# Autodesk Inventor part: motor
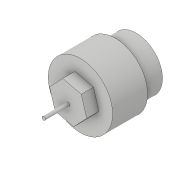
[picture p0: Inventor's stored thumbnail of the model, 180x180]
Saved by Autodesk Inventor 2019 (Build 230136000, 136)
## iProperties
Created: 2019-10
Part Number: motor
Material: Generic
Document SubType Name: Modeling
Designer: hp
Density: 1 g/cm^3
Appearance: Default
Author: hp
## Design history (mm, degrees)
sketch "Sketch1"
  geometry: C1 r 18.449 at (0, 0); 7 further points
  constraints: 1 centre point, 1 coincident
  dimensions: "d0" = 30 distance of point (24.8, -27.876) point (-5.2, -27.876); "d1" = 35 distance of point (24.8, 7.124) point (24.8, -27.876); "d3" = 30 distance of point (17.499, -17.8) point (-12.501, -17.8); "d4" = 30 distance of point (17.499, 12.2) point (17.499, -17.8)
extrude "Extrusion1" new body sketch "Sketch1" distance "d8" = 20; taper "d9" = 0 deg
sketch "Sketch2"
  geometry: L1 (-3.107, 10.442)-(7.489, 7.912); L2 (7.489, 7.912)-(10.596, -2.53); L3 (10.596, -2.53)-(3.107, -10.442); L4 (3.107, -10.442)-(-7.489, -7.912); L5 (-7.489, -7.912)-(-10.596, 2.53); L6 (-10.596, 2.53)-(-3.107, 10.442); 2 further points
  constraints: 12 end point, 1 coincident, 13 other
extrude "Extrusion2" join sketch "Sketch2" distance "d10" = 7; taper "d11" = 0 deg
sketch "Sketch3"
  geometry: C1 r 1 at (0, 0); 1 further point
  constraints: 1 centre point
  dimensions: "d12" = 2 diameter of C1
extrude "Extrusion3" join sketch "Sketch3" distance "d13" = 14; taper "d14" = 0 deg
sketch "Sketch4"
  geometry: C1 r 15.015 at (0, 0); 2 further points
  constraints: 1 centre point, 1 coincident
extrude "Extrusion4" join sketch "Sketch4" distance "d15" = 12; taper "d16" = 0 deg
body "Solid1"
